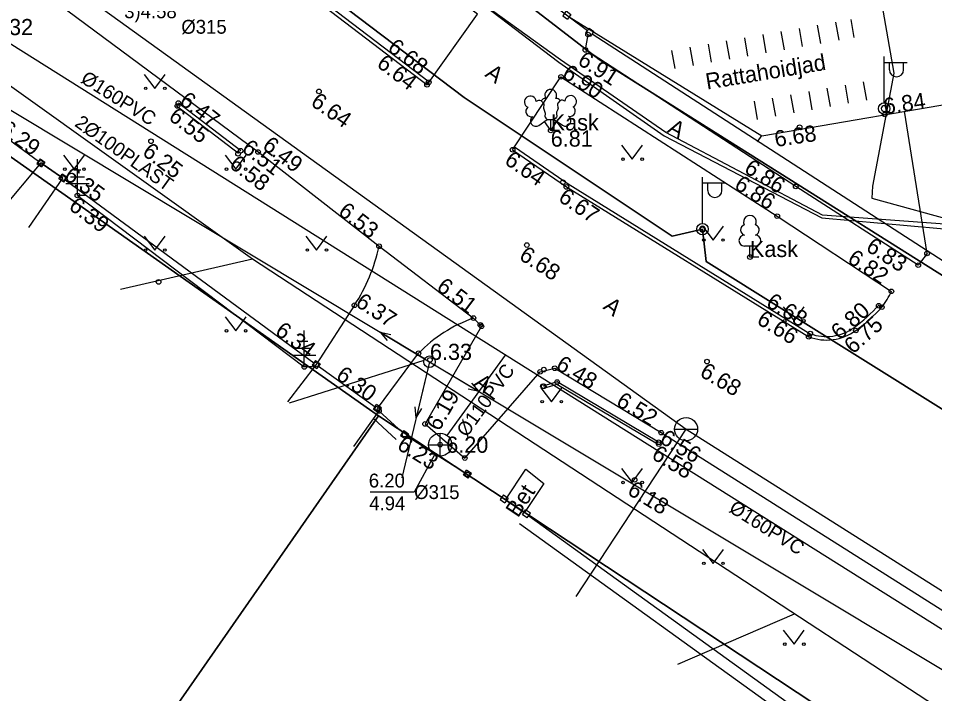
# Model space of a CAD drawing. Extents: x 473307 to 473719, y 6532843 to 6533381.
# Drawn here: x 473506.36 to 473546.03, y 6532942.76 to 6532972 of the extents above; entities that cross this region are included whole.
import ezdxf

# ---------------------------------------------------------------- set-up
doc = ezdxf.new("R2010")
doc.units = 0
for name, color, linetype in [('AED', 7, 'Continuous'), ('Default', 7, 'Continuous'), ('DKAEV_NR', 7, 'Continuous'), ('HALJASTUS', 7, 'Continuous'), ('KKAEV', 7, 'Continuous'), ('KKAEV_NR', 7, 'Continuous'), ('KORGUS', 7, 'Continuous'), ('KPKAABEL', 7, 'Continuous'), ('KTRASS', 7, 'Continuous'), ('KTRASS_TEKST', 7, 'Continuous'), ('MPKAABEL', 7, 'Continuous'), ('MPOHULIIN', 7, 'Continuous'), ('PIIR', 7, 'Continuous'), ('POST', 7, 'Continuous'), ('PUU', 7, 'Continuous'), ('RAJATIS', 7, 'Continuous'), ('SITRASS', 7, 'Continuous'), ('SITRASS_TEKST', 7, 'Continuous'), ('TEE', 7, 'Continuous'), ('VKAEV', 7, 'Continuous'), ('VTRASS', 7, 'Continuous')]:
    doc.layers.add(name, color=color, linetype=linetype)

# ---------------------------------------------------------------- blocks, each defined once
blk = doc.blocks.new('VARPOS')
at = {"layer": 'Default'}
for p, q in [((-0.25, 0.25), (-0.25, -0.25)), ((-0.25, 0.25), (0.25, 0.25)), ((0.25, 0.25), (0.25, -0.25)), ((-0.25, -0.25), (0.25, -0.25))]:
    blk.add_line(p, q, dxfattribs=at)
blk = doc.blocks.new('MEPOST')
at = {"layer": 'Default'}
blk.add_circle((0, 0), 0.5, dxfattribs=at)
for start, end in [(0, 180), (180, 0)]:
    blk.add_arc((0, 0), 0.25, start, end, dxfattribs=at)
blk = doc.blocks.new('VAPOST')
at = {"layer": 'Default'}
for p, q in [((0, 0.5), (0, 4.5)), ((0, 4), (2, 4)), ((0.453, 3.358), (0.453, 4)), ((1.679, 3.358), (1.679, 4))]:
    blk.add_line(p, q, dxfattribs=at)
blk.add_arc((1.066, 3.358), 0.613, 180, 0, dxfattribs=at)
blk = doc.blocks.new('PUPOST')
at = {"layer": 'Default'}
blk.add_circle((0, 0), 0.5, dxfattribs=at)
blk = doc.blocks.new('LEHTP1')
at = {"layer": 'Default'}
for p, q in [((0.48, 0.95), (-0.48, 0.95)), ((0, 0), (0, 0.95)), ((0.76, 0), (0, 0))]:
    blk.add_line(p, q, dxfattribs=at)
for centre, radius, start, end in [((0, 3.04), 0.554, 332.5799, 207.4201), ((-0.34, 2.345), 0.465, 109.02174, 253.14154), ((0.34, 2.345), 0.465, 286.85082, 70.98591), ((-0.475, 1.425), 0.475, 90.0016, 269.3953), ((0.475, 1.425), 0.475, 270.6047, 89.9984)]:
    blk.add_arc(centre, radius, start, end, dxfattribs=at)
blk = doc.blocks.new('LEHTP3')
at = {"layer": 'Default'}
for p, q in [((-1.02, 0.44), (-0.3, 0.95)), ((-0.3, 0.95), (0.29, 0.95)), ((0, 0), (0, 0.95)), ((0.29, 0.95), (1.01, 0.46)), ((0, 0), (-0.55, 0.77)), ((0, 0), (0.54, 0.78)), ((0.76, 0), (0, 0))]:
    blk.add_line(p, q, dxfattribs=at)
for points in [[(-0.825, 2.575), (-0.62, 2.37), (-0.59, 2.31), (-0.59, 2.2), (-0.62, 2.02), (-0.62, 1.93), (-0.58, 1.77), (-0.5, 1.59), (-0.48, 1.5), (-0.49, 1.41), (-0.52, 1.28), (-0.52, 1.22), (-0.48, 1.14), (-0.43, 1.08), (-0.3, 0.95)], [(0.808, 2.603), (0.62, 2.37), (0.59, 2.31), (0.59, 2.2), (0.62, 2.02), (0.63, 1.93), (0.59, 1.77), (0.51, 1.59), (0.49, 1.5), (0.5, 1.41), (0.53, 1.28), (0.53, 1.22), (0.49, 1.14), (0.44, 1.08), (0.3, 0.95)]]:
    blk.add_lwpolyline(points, dxfattribs=at)
for centre, radius, start, end in [((0, 3.04), 0.512, 90.00126, 211.01588), ((0, 3.04), 0.512, 328.98412, 89.99874), ((-1.767, 2.474), 0.512, 125.53894, 246.55356), ((-1.767, 2.474), 0.512, 4.5218, 125.53642), ((-0.994, 2.209), 0.403, 65.23821, 130.74121), ((-0.475, 2.375), 0.403, 84.79647, 150.29947), ((0.475, 2.375), 0.403, 34.38566, 95.20353), ((0.953, 2.227), 0.403, 50.31726, 111.13512), ((1.721, 2.506), 0.512, 55.52204, 176.53666), ((1.721, 2.506), 0.512, 294.50491, 55.51952), ((-1.711, 1.64), 0.448, 125.46665, 288.53492), ((1.68, 1.671), 0.448, 252.52354, 55.59181), ((-1.292, 0.828), 0.475, 125.53768, 305.53661), ((1.277, 0.852), 0.475, 235.52186, 55.52078)]:
    blk.add_arc(centre, radius, start, end, dxfattribs=at)
blk = doc.blocks.new('VEKAEV')
at = {"layer": 'Default'}
blk.add_line((-1, 0), (1, 0), dxfattribs=at)
blk.add_circle((0, 0), 1, dxfattribs=at)
blk = doc.blocks.new('KAKAEV')
at = {"layer": 'Default'}
for p, q in [((0, -1), (0, 1)), ((-1, 0), (1, 0))]:
    blk.add_line(p, q, dxfattribs=at)
blk.add_circle((0, 0), 1, dxfattribs=at)
blk = doc.blocks.new('OKASP1')
at = {"layer": 'Default'}
for p, q in [((0, 0), (0, 3.15)), ((0.6, 1.6), (-0.6, 1.6)), ((0.3, 2.2), (-0.3, 2.2)), ((1, 1), (-1, 1)), ((0.72, 0), (0, 0))]:
    blk.add_line(p, q, dxfattribs=at)
blk = doc.blocks.new('MURU')
at = {"layer": 'Default'}
for p, q in [((-0.927, 1.213), (0, 0)), ((0, 0), (0.891, 1.213))]:
    blk.add_line(p, q, dxfattribs=at)
for centre in [(-0.802, 0), (0.856, 0)]:
    blk.add_circle(centre, 0.11, dxfattribs=at)
blk = doc.blocks.new('MPSUUN')
at = {"layer": 'Default'}
for p, q in [((0.5, 0), (5, 0)), ((5, 0), (4.097, -0.297)), ((5, 0), (4.098, 0.3))]:
    blk.add_line(p, q, dxfattribs=at)

msp = doc.modelspace()

# ---------------------------------------------------------------- linework, layer by layer
at = {"layer": 'AED'}
msp.add_line((473522.985, 6532954.06), (473521.966, 6532954.998), dxfattribs=at)
for points in [[(473530.2, 6532972.069), (473530.991, 6532971.474)], [(473531.197, 6532971.332), (473546.442, 6532961.469)], [(473499.397, 6532967.942), (473501.537, 6532969.99), (473507.228, 6532965.81)], [(473507.434, 6532965.669), (473508.185, 6532965.151)], [(473508.39, 6532965.008), (473519.151, 6532957.083)], [(473519.355, 6532956.937), (473521.799, 6532955.171)], [(473521.966, 6532954.998), (473520.864, 6532953.464)], [(473523.184, 6532953.908), (473525.697, 6532952.325)], [(473525.904, 6532952.185), (473527.277, 6532951.259)], [(473527.487, 6532951.123), (473528.25, 6532950.607)], [(473528.455, 6532950.464), (473540.262, 6532941.941), (473539.541, 6532940.843)]]:
    msp.add_lwpolyline(points, dxfattribs=at)
at = {"layer": 'HALJASTUS'}
msp.add_line((473522.714, 6532953.766), (473521.738, 6532954.665), dxfattribs=at)
for points in [[(473508.917, 6532964.328), (473518.738, 6532956.906)], [(473528.061, 6532950.132), (473539.987, 6532941.523)]]:
    msp.add_lwpolyline(points, dxfattribs=at)
at = {"layer": 'KKAEV_NR'}
msp.add_lwpolyline([(473524.38, 6532953.099), (473523.495, 6532951.485), (473521.592, 6532951.485)], dxfattribs=at)
at = {"layer": 'KORGUS'}
for centre in [(473531.02, 6532971.3), (473530.905, 6532970.63), (473529.85, 6532969.466), (473524.055, 6532969.123), (473524.127, 6532969.232), (473519.371, 6532968.836), (473513.287, 6532968.328), (473513.242, 6532968.203), (473543.866, 6532967.837), (473529.406, 6532967.143), (473540.181, 6532967.287), (473512.101, 6532966.675), (473515.984, 6532966.265), (473527.756, 6532966.309), (473515.871, 6532966.137), (473516.735, 6532966.211), (473507.331, 6532965.739), (473508.29, 6532965.082), (473529.936, 6532964.903), (473530.085, 6532964.701), (473540.015, 6532964.72), (473508.917, 6532964.328), (473539.211, 6532963.431), (473535.978, 6532962.869), (473521.977, 6532962.129), (473528.372, 6532962.183), (473538.031, 6532961.662), (473538.031, 6532961.662), (473538.031, 6532961.662), (473538.031, 6532961.662), (473545.7, 6532961.821), (473545.318, 6532961.312), (473512.43, 6532960.584), (473544.156, 6532960.177), (473520.909, 6532959.573), (473543.607, 6532959.553), (473543.739, 6532959.491), (473526.063, 6532959.019), (473526.362, 6532958.727), (473526.41, 6532958.663), (473540.64, 6532958.347), (473542.616, 6532958.482), (473540.576, 6532958.208), (473523.682, 6532957.495), (473524.177, 6532957.207), (473536.171, 6532957.135), (473518.738, 6532956.906), (473519.253, 6532957.01), (473529.106, 6532956.788), (473529.581, 6532956.846), (473528.95, 6532956.691), (473529.064, 6532956.068), (473529.105, 6532956.068), (473529.684, 6532956.253), (473521.902, 6532955.101), (473521.966, 6532954.998), (473523.968, 6532954.435), (473523.078, 6532953.974), (473534.188, 6532954.059), (473534.077, 6532953.642), (473534.086, 6532953.561), (473524.621, 6532953.538), (473525.686, 6532952.96), (473525.8, 6532952.255), (473533.039, 6532952.016)]:
    msp.add_circle(centre, 0.1, dxfattribs=at)
at = {"layer": 'KPKAABEL'}
msp.add_lwpolyline([(473552.428, 6532965.743), (473551.926, 6532964.369), (473550.859, 6532963.61), (473549.116, 6532963.304), (473547.25, 6532963.025), (473541.17, 6532963.479), (473534.383, 6532967.06), (473529.823, 6532970.204), (473517.524, 6532979.079), (473506.639, 6532987.521), (473501.292, 6532992.893), (473495.73, 6532998.121), (473498.407, 6533003.379)], dxfattribs=at)
at = {"layer": 'KTRASS'}
for p, q in [((473505.335, 6532971.329), (473560.125, 6532936.877)), ((473524.916, 6532953.942), (473527.455, 6532957.42))]:
    msp.add_line(p, q, dxfattribs=at)
at = {"layer": 'MPKAABEL'}
for points in [[(473592.161, 6532931.655), (473583.871, 6532934.989), (473574.572, 6532939.314), (473574.03, 6532940.034), (473574.304, 6532941.029), (473573.472, 6532940.172), (473563.473, 6532945.174), (473556.129, 6532949.371), (473546.422, 6532955.029), (473536.136, 6532961.464), (473535.978, 6532962.869), (473534.663, 6532962.568), (473525.661, 6532968.571), (473517.097, 6532975.071), (473509.151, 6532981.519), (473503.051, 6532987.775), (473502.694, 6532988.631), (473501.293, 6532988.874), (473494.528, 6532995.717), (473488.455, 6533001.872), (473481.096, 6533010.082), (473475.299, 6533017.476)], [(473488.425, 6533006.486), (473501.71, 6533000.864), (473517.757, 6532996.211), (473517.757, 6532996.211), (473517.757, 6532996.211), (473533.632, 6532991.468), (473540.569, 6532989.326), (473541.046, 6532988.945), (473541.043, 6532988.058), (473544.258, 6532969.621), (473543.338, 6532964.734), (473543.314, 6532964.208), (473547.196, 6532963.14), (473550.121, 6532963.651), (473551.828, 6532964.446), (473552.375, 6532965.735)], [(473502.694, 6532988.631), (473503.051, 6532987.775), (473509.151, 6532981.519), (473517.097, 6532975.071), (473525.661, 6532968.571), (473534.663, 6532962.568), (473535.978, 6532962.869)], [(473493.252, 6532975.715), (473497.24, 6532978.112), (473498.183, 6532979.06), (473499.269, 6532980.163), (473501.448, 6532982.423), (473503.504, 6532984.545), (473505.843, 6532986.884), (473507.45, 6532987.966), (473517.665, 6532979.32), (473529.752, 6532970.098), (473534.316, 6532966.914), (473541.139, 6532963.364), (473547.56, 6532962.777), (473549.436, 6532962.995), (473552.396, 6532963.548), (473552.501, 6532963.798), (473552.517, 6532963.893), (473552.555, 6532965.764)], [(473535.978, 6532962.869), (473536.136, 6532961.464), (473546.422, 6532955.029), (473556.129, 6532949.371), (473563.473, 6532945.174), (473573.472, 6532940.172), (473574.304, 6532941.029)], [(473523.915, 6532957.181), (473518.083, 6532955.34)]]:
    msp.add_lwpolyline(points, dxfattribs=at)
at = {"layer": 'MPOHULIIN'}
for points in [[(473423.194, 6533272.897), (473391.791, 6533270.484), (473361.09, 6533267.919), (473364.229, 6533220.925), (473380.477, 6533175.317), (473396.165, 6533131.758), (473413.567, 6533083.532), (473430.968, 6533052.6), (473459.84, 6533016.944), (473493.252, 6532975.715), (473524.159, 6532957.128), (473561.498, 6532934.712), (473599.705, 6532914.54), (473648.184, 6532910.183)], [(473524.159, 6532957.128), (473522.956, 6532952.103)]]:
    msp.add_lwpolyline(points, dxfattribs=at)
at = {"layer": 'PIIR'}
for points in [[(473486.57, 6533007.64), (473478.82, 6533017), (473548.5, 6533028.91), (473572.63, 6533056.43), (473618.6, 6533063.82), (473630.89, 6533065.72), (473654.16, 6532926.37), (473652.82, 6532924.82), (473637.7, 6532924.6), (473625.07, 6532926.73), (473607.63, 6532930.98), (473579.04, 6532941.93), (473554.34, 6532955.84), (473531.51, 6532970.21), (473509.62, 6532987.09)], [(473501.05, 6532969.5), (473521.95, 6532954.78), (473504.05, 6532929.11), (473479.39, 6532947.34)], [(473521.95, 6532954.78), (473540.88, 6532942.28), (473523.99, 6532915.67), (473504.05, 6532929.11)]]:
    msp.add_lwpolyline(points, close=True, dxfattribs=at)
msp.add_lwpolyline([(473455.33, 6533045.76), (473478.82, 6533017), (473486.57, 6533007.64), (473509.62, 6532987.09), (473531.51, 6532970.21), (473554.34, 6532955.84), (473579.04, 6532941.93), (473607.63, 6532930.98), (473625.07, 6532926.73), (473637.7, 6532924.6), (473652.82, 6532924.82), (473654.16, 6532926.37), (473664.64, 6532927.81), (473668.24, 6532906.4), (473641.69, 6532906.33), (473620.6, 6532909.02), (473600.1, 6532914.5), (473579.89, 6532922.16), (473559.95, 6532931.3), (473540.88, 6532942.28), (473521.95, 6532954.78), (473501.05, 6532969.5), (473492.55, 6532977.62), (473473.12, 6532997.79)], dxfattribs=at)
at = {"layer": 'RAJATIS'}
for points in [[(473542.548, 6532971.163), (473542.411, 6532971.951)], [(473540.31, 6532970.776), (473540.174, 6532971.564)], [(473541.099, 6532970.912), (473540.962, 6532971.701)], [(473541.887, 6532971.049), (473541.751, 6532971.837)], [(473537.945, 6532970.367), (473537.809, 6532971.155)], [(473538.734, 6532970.503), (473538.597, 6532971.292)], [(473539.522, 6532970.64), (473539.386, 6532971.428)], [(473535.58, 6532969.958), (473535.444, 6532970.746)], [(473536.369, 6532970.094), (473536.232, 6532970.883)], [(473537.157, 6532970.231), (473537.021, 6532971.019)], [(473534.792, 6532969.822), (473534.656, 6532970.61)], [(473543.084, 6532968.458), (473542.944, 6532969.246)], [(473540.727, 6532968.04), (473540.588, 6532968.828)], [(473541.515, 6532968.18), (473541.375, 6532968.968)], [(473542.303, 6532968.32), (473542.163, 6532969.107)], [(473538.364, 6532967.621), (473538.225, 6532968.409)], [(473539.152, 6532967.761), (473539.012, 6532968.549)], [(473539.94, 6532967.901), (473539.8, 6532968.688)]]:
    msp.add_lwpolyline(points, dxfattribs=at)
at = {"layer": 'SITRASS'}
msp.add_line((473510.778, 6532960.267), (473516.49, 6532961.585), dxfattribs=at)
for points in [[(473494.734, 6532977.145), (473516.49, 6532961.585), (473549.65, 6532939.871)], [(473534.906, 6532944.041), (473539.962, 6532946.215)]]:
    msp.add_lwpolyline(points, dxfattribs=at)
at = {"layer": 'TEE'}
for points in [[(473524.055, 6532969.123), (473526.237, 6532972.185), (473521.261, 6532975.911), (473517.583, 6532978.66), (473512.426, 6532982.575)], [(473512.435, 6532978.347), (473512.649, 6532977.896), (473513.434, 6532977.231), (473524.055, 6532969.123)], [(473512.571, 6532978.411), (473512.771, 6532977.99), (473513.528, 6532977.348), (473524.142, 6532969.245)], [(473525.421, 6532975.868), (473525.421, 6532975.868), (473526.918, 6532974.688), (473526.846, 6532974.587), (473530.2, 6532972.069), (473538.549, 6532966.914)], [(473507.269, 6532973.243), (473516.735, 6532966.211), (473521.977, 6532962.129), (473526.063, 6532959.019), (473526.41, 6532958.663), (473523.968, 6532954.435), (473525.686, 6532952.96), (473528.95, 6532956.691), (473529.581, 6532956.846), (473534.188, 6532954.059), (473548.771, 6532944.84), (473558.935, 6532938.993), (473557.576, 6532936.09)], [(473545.7, 6532961.821), (473545.318, 6532961.312), (473540.015, 6532964.72), (473530.905, 6532970.63), (473531.02, 6532971.3)], [(473527.756, 6532966.309), (473529.85, 6532969.466), (473539.211, 6532963.431), (473544.156, 6532960.177)], [(473515.984, 6532966.265), (473513.287, 6532968.328)], [(473538.549, 6532966.914), (473548.313, 6532968.59)], [(473515.893, 6532966.146), (473513.196, 6532968.208)], [(473545.7, 6532961.821), (473544.726, 6532967.974)], [(473538.525, 6532966.93), (473538.349, 6532966.656)], [(473527.836, 6532966.437), (473527.844, 6532966.43), (473530.167, 6532964.827), (473540.642, 6532958.343)], [(473527.756, 6532966.309), (473530.085, 6532964.701), (473540.576, 6532958.208)], [(473506.808, 6532962.945), (473508.29, 6532965.082), (473507.331, 6532965.739), (473505.648, 6532963.727)], [(473520.909, 6532959.573), (473519.253, 6532957.01), (473518.009, 6532955.39)], [(473521.902, 6532955.101), (473523.682, 6532957.495)], [(473534.077, 6532953.642), (473529.684, 6532956.253), (473529.064, 6532956.068)], [(473534.026, 6532953.556), (473529.671, 6532956.145), (473529.092, 6532955.972)], [(473527.452, 6532951.147), (473528.328, 6532952.474), (473529.105, 6532951.862), (473528.274, 6532950.604)], [(473527.452, 6532951.147), (473528.328, 6532952.474), (473529.105, 6532951.862), (473528.274, 6532950.604)]]:
    msp.add_lwpolyline(points, dxfattribs=at)
for centre, radius, start, end in [((473514.331, 6532963.824), 7.832, 327.128, 347.5015), ((473541.087, 6532961.573), 3.371, 321.8678, 335.5438), ((473537.802, 6532964.969), 7.928, 306.5855, 317.3009), ((473537.802, 6532964.969), 8.078, 306.5776, 317.3009), ((473528.101, 6532953.215), 6.151, 109.3485, 135.9177), ((473541.339, 6532960.255), 2.185, 249.5478, 305.7518), ((473541.339, 6532960.255), 2.035, 249.9585, 305.7218)]:
    msp.add_arc(centre, radius, start, end, dxfattribs=at)
at = {"layer": 'VTRASS'}
for points in [[(473503.731, 6532976.927), (473535.265, 6532954.21), (473555.891, 6532941.175), (473565.122, 6532936.508), (473600.672, 6532921.587), (473636.512, 6532914.617), (473674.923, 6532915.363), (473675.557, 6532915.427)], [(473530.505, 6532946.962), (473535.265, 6532954.21)]]:
    msp.add_lwpolyline(points, dxfattribs=at)

# ---------------------------------------------------------------- block references
at = {"layer": 'AED'}
for p, xscale, yscale, rotation in [((473530.099, 6532972.142), 0.5, 0.5, -35.542607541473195), ((473531.093, 6532971.402), 0.5, 0.5, -35.542607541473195), ((473507.331, 6532965.739), 0.49999999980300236, 0.49999999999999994, -34.476326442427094), ((473508.29, 6532965.082), 0.4999999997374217, 0.5000000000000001, 146.56659852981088), ((473519.253, 6532957.01), 0.5000000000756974, 0.5, -35.59892549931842), ((473521.902, 6532955.101), 0.5000000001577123, 0.5, 145.84601405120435), ((473523.078, 6532953.974), 0.4999999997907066, 0.5000000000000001, -34.168013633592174), ((473525.8, 6532952.255), 0.500000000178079, 0.5, 145.86006041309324), ((473527.385, 6532951.195), 0.4999999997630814, 0.5, -35.24830330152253), ((473528.354, 6532950.537), 0.4999999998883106, 0.49999999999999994, 146.17342081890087)]:
    msp.add_blockref('VARPOS', p, dxfattribs=dict(at, xscale=xscale, yscale=yscale, rotation=rotation))
at = {"layer": 'HALJASTUS', "xscale": 0.5, "yscale": 0.5}
for p in [(473512.271, 6532968.967), (473532.938, 6532965.899), (473508.771, 6532965.467), (473515.771, 6532965.467), (473536.438, 6532962.399), (473512.271, 6532961.967), (473519.271, 6532961.967), (473539.938, 6532958.899), (473515.771, 6532958.467), (473529.438, 6532955.399), (473532.938, 6532951.899), (473536.438, 6532948.399), (473539.938, 6532944.899)]:
    msp.add_blockref('MURU', p, dxfattribs=at)
at = {"layer": 'KKAEV', "xscale": 0.5, "yscale": 0.5}
msp.add_blockref('KAKAEV', (473524.621, 6532953.538), dxfattribs=at)
at = {"layer": 'MPOHULIIN'}
for xscale, yscale, rotation in [(0.49999999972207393, 0.5000000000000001, 148.9779385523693), (0.499999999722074, 0.49999999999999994, -103.46013716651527), (0.4999999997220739, 0.49999999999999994, -30.977970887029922)]:
    msp.add_blockref('MPSUUN', (473524.159, 6532957.128), dxfattribs=dict(at, xscale=xscale, yscale=yscale, rotation=rotation))
at = {"layer": 'POST', "xscale": 0.5, "yscale": 0.5}
for name, p in [('VAPOST', (473543.842, 6532968.091)), ('MEPOST', (473543.842, 6532968.091)), ('VAPOST', (473535.978, 6532962.869)), ('MEPOST', (473535.978, 6532962.869)), ('PUPOST', (473524.159, 6532957.128))]:
    msp.add_blockref(name, p, dxfattribs=at)
at = {"layer": 'PUU', "xscale": 0.5, "yscale": 0.5}
for name, p in [('LEHTP3', (473529.406, 6532967.143)), ('OKASP1', (473508.917, 6532964.328)), ('LEHTP1', (473538.031, 6532961.662)), ('OKASP1', (473518.738, 6532956.906))]:
    msp.add_blockref(name, p, dxfattribs=at)
at = {"layer": 'VKAEV', "xscale": 0.5, "yscale": 0.5}
msp.add_blockref('VEKAEV', (473535.265, 6532954.21), dxfattribs=at)

# ---------------------------------------------------------------- texts
at = {"layer": 'DKAEV_NR'}
msp.add_text('%%c315', height=0.6, dxfattribs=at).set_placement((473513.414, 6532971.332))
at = {"layer": 'KKAEV_NR'}
for s, p in [('3)4.58', (473510.94, 6532972.004)), ('6.20', (473521.529, 6532951.685)), ('%%c315', (473523.495, 6532951.185)), ('4.94', (473521.548, 6532950.699))]:
    msp.add_text(s, height=0.6, dxfattribs=at).set_placement(p)
at = {"layer": 'KORGUS'}
for s, p in [(' 6.32', (473504.914, 6532971.272)), ('6.81', (473529.406, 6532966.443)), ('6.33', (473524.177, 6532957.207)), (' 6.20', (473524.621, 6532953.188))]:
    msp.add_text(s, height=0.7, dxfattribs=at).set_placement(p)
for s, rotation, p in [('6.68', 322.6421, (473522.299, 6532970.628)), ('6.64', 322.6421, (473521.829, 6532969.942)), ('6.91', 327.027, (473530.524, 6532970.043)), ('6.90', 327.1903, (473529.85, 6532969.466)), ('6.47', 322.586, (473513.287, 6532968.328)), ('6.64', 325, (473518.97, 6532968.262)), ('6.84', 8.1561, (473543.866, 6532967.837)), ('6.55', 322.586, (473512.817, 6532967.647)), ('6.29', 323.7081, (473505.504, 6532967.081)), ('6.68', 8.4889, (473539.147, 6532966.425)), ('6.49', 322.0946, (473516.878, 6532966.395)), ('6.25', 323, (473511.68, 6532966.116)), ('6.51', 322.586, (473515.984, 6532966.265)), ('6.58', 322.586, (473515.446, 6532965.581)), ('6.64', 325.3874, (473527.358, 6532965.733)), ('6.35', 323.6304, (473508.29, 6532965.082)), ('6.86', 327.027, (473537.732, 6532965.366)), ('6.86', 327.1903, (473537.306, 6532964.659)), ('6.67', 325.6145, (473529.69, 6532964.124)), ('6.39', 322.9234, (473508.495, 6532963.769)), ('6.53', 322.0946, (473520.163, 6532963.542)), ('6.83', 327.273, (473543.005, 6532961.967)), ('6.68', 327.0876, (473527.991, 6532961.595)), ('6.82', 326.6535, (473542.207, 6532961.46)), ('6.51', 322.7245, (473524.419, 6532960.271)), ('6.37', 326.7819, (473520.909, 6532959.573)), ('6.68', 328.2439, (473538.684, 6532959.557)), ('6.80', 42, (473541.923, 6532958.036)), ('6.66', 328.2439, (473538.28, 6532958.806)), ('6.34', 323.6375, (473517.428, 6532958.354)), ('6.75', 41.9393, (473542.496, 6532957.433)), ('6.48', 328.8252, (473529.581, 6532956.846)), ('6.30', 324.1495, (473520.065, 6532956.429)), ('6.68', 329.3038, (473535.813, 6532956.533)), ('6.19', 59.9908, (473524.574, 6532954.085)), ('6.52', 328.8252, (473532.192, 6532955.266)), ('6.56', 329.2693, (473534.077, 6532953.642)), ('6.23', 327.7949, (473522.705, 6532953.382)), ('6.58', 329.2693, (473533.728, 6532952.959)), ('6.18', 328.8324, (473532.677, 6532951.417))]:
    msp.add_text(s, height=0.7, rotation=rotation, dxfattribs=at).set_placement(p)
at = {"layer": 'KTRASS_TEKST'}
for s, rotation, p in [('%%c160PVC', 327.8383, (473509.016, 6532969.251)), ('%%c110PVC', 54.3248, (473525.77, 6532953.826)), ('%%c160PVC', 327.8383, (473537.081, 6532950.658))]:
    msp.add_text(s, height=0.6, rotation=rotation, dxfattribs=at).set_placement(p)
at = {"layer": 'PUU'}
for p in [(473529.406, 6532967.143), (473538.031, 6532961.662)]:
    msp.add_text('Kask', height=0.7, dxfattribs=at).set_placement(p)
at = {"layer": 'RAJATIS'}
msp.add_text('Rattahoidjad', height=0.7, rotation=9.418, dxfattribs=at).set_placement((473536.171, 6532968.913))
at = {"layer": 'SITRASS_TEKST'}
msp.add_text('2%%C100PLAST', height=0.6, rotation=324.4281, dxfattribs=at).set_placement((473508.757, 6532967.362))
at = {"layer": 'TEE'}
for s, rotation, p in [('A', 323.9155, (473526.521, 6532969.514)), ('A', 329.9712, (473534.414, 6532967.086)), ('A', 321.2593, (473531.635, 6532959.451)), ('A', 322.5101, (473526.031, 6532956.125)), ('Bet', 56.5699, (473527.989, 6532950.345)), ('Bet', 56.5699, (473527.989, 6532950.345))]:
    msp.add_text(s, height=0.7, rotation=rotation, dxfattribs=at).set_placement(p)

doc.saveas('drawing.dxf')
